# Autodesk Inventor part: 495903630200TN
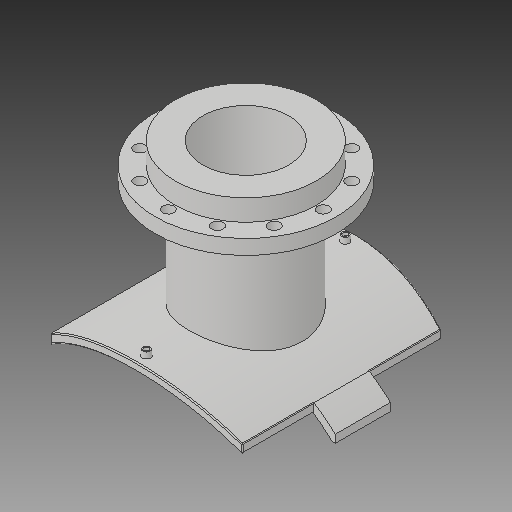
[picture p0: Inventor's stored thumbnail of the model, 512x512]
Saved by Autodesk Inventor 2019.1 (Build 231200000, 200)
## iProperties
Created: 2017-10
Part Number: 495903630200TN
Material: Generic
Description: PLASSON FLANGED BRANCH SADDLE 500-630X200
Document SubType Name: Modeling
Designer: KIM
Mass: 2339.99 g
Surface Area: 3251.55 cm^2
Volume: 2339.99 cm^3
Density: 1 g/cm^3
Appearance: Default
Author: KIM
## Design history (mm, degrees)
derived "495904_495903.ipt"
feature "Solid1::495904_495903.ipt"
feature "Solid2::495904_495903.ipt"
tag "TaggingFeature1"
body "Solid1"
other parameters: "d1" = 15, "d2" = 364.5, "d4" = 0, "d6" = 105, "d7" = 0, "d12" = 340.6, "d13" = 14, "d14" = 189, "d16" = 5 deg, "d18" = 4, "d19" = 14, "d20" = 0, "d21" = 3, "d22" = 0, "d23" = 605, "d36" = 189, "d38" = 0, "d39" = 2, "d41" = 163, "d42" = 268, "d43" = 344, "d46" = 214.4, "d47" = 16, "d48" = 10.4, "d49" = 192.5, "d51" = 642.6, "d53" = 0, "d54" = 22, "d55" = 147.5, "d57" = 0, "d59" = 360 deg, "d61" = 28, "d63" = 0, "d66" = 275, "d67" = 15, "d68" = 137.5, "d70" = 0, "d71" = 2, "d72" = 405, "d_1" = 268, "B_" = 405, "H_" = 275, "x_" = 15, "D_" = 16, "DN_" = 163, "D_1" = 344, "t_" = 28, "s_" = 22, "Dp_" = 295
